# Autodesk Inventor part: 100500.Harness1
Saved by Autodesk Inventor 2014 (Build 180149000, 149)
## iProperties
GlobalPropertyList: <PropertyList><Property propid="Custom" name="desc1" type="14107" originalName="DESC1"/><Property propid="Custom" name="desc2" type="14107" originalName="DESC2"
Key:2|1|1|0|4|0|0|0|57|0|0|0|Level:2: <CableProperty entityType="Connector" version="1.0"><ID editable="" value=""/><UserDefined><Property name="DESC1" value="HORIZONTAL" unitCategory="14107" custom
Key:2|1|1|0|4|0|0|0|58|0|0|0|Level:2: <CableProperty entityType="Connector" version="1.0"><ID editable="" value=""/><UserDefined><Property name="DESC1" value="REAR VERTICAL" unitCategory="14107" cus
Key:2|1|1|0|4|0|0|0|56|0|0|0|Level:2: <CableProperty entityType="Connector" version="1.0"><ID editable="" value=""/><UserDefined><Property name="DESC1" value="FRONT VERTICAL" unitCategory="14107" cu
Key:2|1|1|0|4|0|0|0|55|0|0|0|Level:2: <CableProperty entityType="Connector" version="1.0"><ID editable="" value=""/><UserDefined><Property name="DESC1" value="POWER SEAT" unitCategory="14107" custom
Key:2|1|1|0|4|0|0|0|59|0|0|0|Level:2: <CableProperty entityType="Connector" version="1.0"><ID editable="" value=""/><UserDefined><Property name="DESC1" value="POWER FOR SEAT" unitCategory="14107" cu
Created: 2009-02
Part Number: 100500.Harness1
Document SubType Name: Modeling
Designer: Autodesk
Material: Generic
Appearance: Default
Author: Autodesk
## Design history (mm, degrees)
workpoint "Work Point5"
workpoint "Work Point6"
workpoint "Work Point7"
workpoint "Work Point8"
workpoint "Work Point9"
workpoint "Work Point10"
workpoint "Work Point11"
sketch "Segment2"
workplane "Work Plane3"
sketch "Sketch3"
  geometry: C1 r 1.854 at (0, 0); 1 further point
  constraints: 1 centre point
feature "SweepSrf3" sketch "Sketch3" dims "d2" = 0
workpoint "Work Point12"
sketch "Segment3"
workpoint "Work Point13"
workplane "Work Plane4"
sketch "Sketch4"
  geometry: C1 r 1.854 at (0, 0); 1 further point
  constraints: 1 centre point
feature "SweepSrf4" sketch "Sketch4" dims "d3" = 0
node "SP1"
workpoint "Work Point15"
workpoint "Work Point16"
sketch "Sketch5"
  geometry: L1 (0, -2.686)-(0, 2.686); A1 r 2.686 centre (0, 0) between (0, 2.686) and (0, -2.686)
  constraints: 2 end point, 2 point on circle, 1 centre point
feature "RevolutionSrf1" sketch "Sketch5" dims angle "d4" = 0 deg
workpoint "Work Point35"
sketch "Segment4"
workplane "Work Plane6"
sketch "Sketch7"
  geometry: C1 r 2.238 at (0, 0); 1 further point
  constraints: 1 centre point
feature "SweepSrf6" sketch "Sketch7" dims "d6" = 0
workpoint "Work Point56"
workpoint "Work Point57"
workpoint "Work Point58"
body "Srf3"
body "Srf4"
body "Srf5"
body "Srf7"
